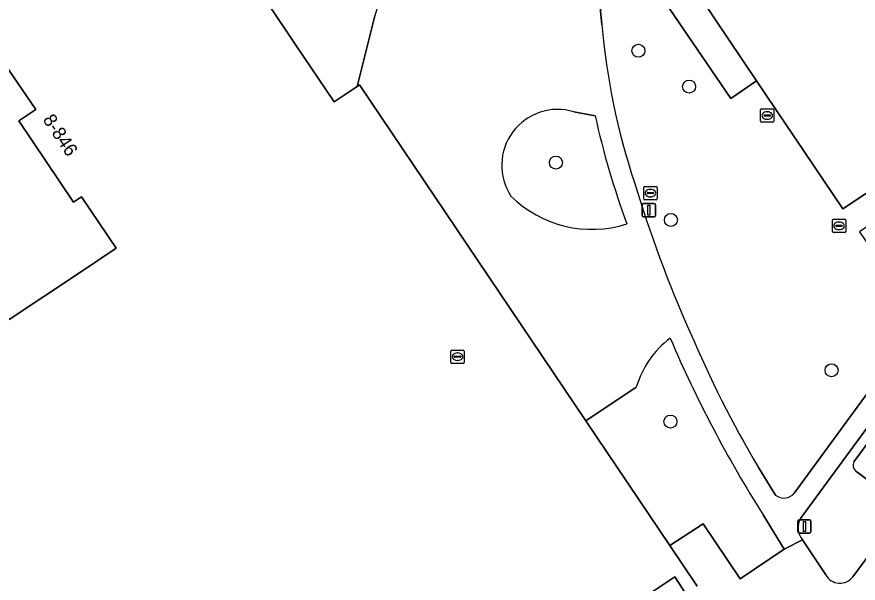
# Model space of a CAD drawing. Extents: x 159674 to 160531, y 382172 to 382904.
# Drawn here: x 159903.8 to 159966.8, y 382436.5 to 382479 of the extents above; entities that cross this region are included whole.
import ezdxf

# ---------------------------------------------------------------- set-up
doc = ezdxf.new("R2010")
doc.units = 0
for name, color, linetype in [('IMGEO_Boom', 7, 'Continuous'), ('IMGEO_Groenvoorziening', 7, 'Continuous'), ('IMGEO_Lichtmast', 7, 'Continuous'), ('IMGEO_Pand', 7, 'Continuous'), ('IMGEO_Pand_nummerreeks', 7, 'Continuous'), ('IMGEO_Parkeervlak_open', 7, 'Continuous'), ('IMGEO_Rijbaan_lokaal_open', 7, 'Continuous'), ('IMGEO_Rioolput', 7, 'Continuous'), ('IMGEO_Voetpad_gesloten', 7, 'Continuous'), ('IMGEO_Voetpad_open', 7, 'Continuous')]:
    doc.layers.add(name, color=color, linetype=linetype)

msp = doc.modelspace()

# ---------------------------------------------------------------- linework, layer by layer
at = {"layer": 'IMGEO_Boom'}
for centre in [(159950.366, 382476.465), (159954.172, 382473.778), (159944.184, 382468.073), (159952.803, 382463.765), (159964.851, 382452.486), (159952.769, 382448.638)]:
    msp.add_circle(centre, 0.489, dxfattribs=at)
at = {"layer": 'IMGEO_Groenvoorziening'}
for points in [[(159981.273, 382465.667), (159991.678, 382480.008), (159991.992, 382480.211), (159996.032, 382477.439), (159996.152, 382477.512), (159986.689, 382484.462), (159983.444, 382482.349), (159980.187, 382487.175), (159978.552, 382485.987), (159984.462, 382477.186), (159972.103, 382468.865), (159965.701, 382464.59), (159959.223, 382474.207), (159957.306, 382472.872), (159952.667, 382479.665), (159953.001, 382479.864), (159952.294, 382480.975), (159952.353, 382481.014), (159951.853, 382481.903), (159947.34, 382481.538), (159947.627, 382478.436)], [(159920.894, 382482.597), (159924.587, 382477.025), (159924.687, 382476.874), (159927.556, 382472.629), (159929.284, 382473.78), (159930.626, 382479.087)], [(159947.126, 382471.589), (159945.534, 382471.883)], [(159983.301, 382457.947), (159982.838, 382458.301), (159982.702, 382459.015), (159983.343, 382459.872), (159980.738, 382461.834), (159979.204, 382464.122), (159962.528, 382441.377)], [(159966.518, 382445.61), (159976.477, 382459.119)], [(159962.082, 382443.294), (159969.303, 382453.181), (159971.096, 382455.701)], [(159950.212, 382451.214), (159946.417, 382448.7)], [(159946.417, 382448.7), (159952.717, 382439.336), (159955.221, 382440.97), (159958.003, 382436.844), (159961.289, 382439.079), (159959.711, 382441.653)], [(159959.365, 382445.206), (159960.65, 382443.114)], [(159969.816, 382442.599), (159966.663, 382444.93)], [(159966.443, 382436.997), (159968.211, 382439.403), (159970.077, 382441.998)], [(159962.665, 382439.764), (159964.416, 382437.134)]]:
    msp.add_lwpolyline(points, dxfattribs=at)
for centre, radius, start, end in [((159999.331, 382482.921), 51.898, 184.95794, 198.35432), ((159944.322, 382467.864), 4.197, 73.2191, 213.32862), ((160010.525, 382485.679), 64.946, 192.53022, 200.00048), ((160041.512, 382494.145), 95.504, 196.77657, 203.95294), ((159946.893, 382471.723), 8.658, 225.40624, 287.49547), ((160032.462, 382488.485), 84.949, 202.94226, 210.62886), ((159957.024, 382449.226), 7.096, 126.99514, 163.73447), ((160039.191, 382491.861), 94.01, 203.15522, 212.28086), ((159966.998, 382445.357), 0.543, 152.19272, 231.88168), ((159961.277, 382443.915), 1.017, 231.9574, 322.37142), ((159963.718, 382440.666), 1.386, 149.12437, 220.58515), ((159965.474, 382437.729), 1.214, 209.34496, 322.92183)]:
    msp.add_arc(centre, radius, start, end, dxfattribs=at)
at = {"layer": 'IMGEO_Lichtmast'}
for p, q in [((159950.659, 382464.101), (159950.659, 382464.901)), ((159950.659, 382464.901), (159950.659, 382464.101)), ((159950.759, 382465.001), (159951.549, 382465.001)), ((159951.549, 382465.001), (159950.759, 382465.001)), ((159951.649, 382464.901), (159951.649, 382464.101)), ((159951.649, 382464.101), (159951.649, 382464.901)), ((159951.549, 382464.001), (159950.759, 382464.001)), ((159950.759, 382464.001), (159951.549, 382464.001)), ((159962.314, 382440.379), (159962.314, 382441.179)), ((159962.314, 382441.179), (159962.314, 382440.379)), ((159962.414, 382441.279), (159963.204, 382441.279)), ((159963.204, 382441.279), (159962.414, 382441.279)), ((159963.304, 382441.179), (159963.304, 382440.379)), ((159963.304, 382440.379), (159963.304, 382441.179)), ((159963.204, 382440.279), (159962.414, 382440.279)), ((159962.414, 382440.279), (159963.204, 382440.279))]:
    msp.add_line(p, q, dxfattribs=at)
for points in [[(159951.079, 382464.876), (159951.229, 382464.876), (159951.229, 382464.126), (159951.079, 382464.126), (159951.079, 382464.876)], [(159962.734, 382441.154), (159962.884, 382441.154), (159962.884, 382440.404), (159962.734, 382440.404), (159962.734, 382441.154)]]:
    msp.add_lwpolyline(points, dxfattribs=at)
for centre, start, end in [((159950.759, 382464.901), 90, 180), ((159950.759, 382464.901), 90, 180), ((159951.549, 382464.901), 0, 90), ((159951.549, 382464.901), 360, 90), ((159950.759, 382464.101), 180, 270), ((159950.759, 382464.101), 180, 270), ((159951.549, 382464.101), 270, 0), ((159951.549, 382464.101), 270, 0), ((159962.414, 382441.179), 90, 180), ((159962.414, 382441.179), 90, 180), ((159963.204, 382441.179), 0, 90), ((159963.204, 382441.179), 360, 90), ((159962.414, 382440.379), 180, 270), ((159962.414, 382440.379), 180, 270), ((159963.204, 382440.379), 270, 0), ((159963.204, 382440.379), 270, 0)]:
    msp.add_arc(centre, 0.1, start, end, dxfattribs=at)
at = {"layer": 'IMGEO_Pand'}
for points in [[(159929.284, 382473.78), (159927.556, 382472.629), (159924.687, 382476.874), (159924.587, 382477.025), (159920.894, 382482.597), (159918.836, 382485.861), (159916.043, 382490.496), (159913.789, 382494.394), (159911.188, 382499.142), (159910.743, 382500), (159908.792, 382503.757), (159906.654, 382508.016), (159905.429, 382510.573), (159921.255, 382524.225), (159921.544, 382524.474), (159921.508, 382524.623), (159920.424, 382529.122), (159913.541, 382527.426), (159914.819, 382522.233), (159904.282, 382513.075), (159904.024, 382512.862), (159902.176, 382511.239)], [(159902.877, 382475.458), (159905.207, 382472.058), (159903.939, 382471.211), (159908.014, 382465.094), (159908.638, 382465.51), (159911.217, 382461.64), (159908.541, 382459.857), (159903.211, 382456.306)], [(159954.77, 382436.285), (159952.717, 382439.336), (159946.417, 382448.7), (159929.473, 382473.906), (159929.284, 382473.78)], [(159943.275, 382430.436), (159953.094, 382436.989), (159953.927, 382435.721)]]:
    msp.add_lwpolyline(points, dxfattribs=at)
msp.add_lwpolyline([(159978.552, 382485.987), (159977.69, 382487.272), (159971.108, 382497.075), (159952.337, 382484.474), (159953.275, 382483.094), (159953.953, 382482.094), (159959.223, 382474.207), (159965.701, 382464.59), (159972.103, 382468.865), (159984.462, 382477.186)], close=True, dxfattribs=at)
at = {"layer": 'IMGEO_Parkeervlak_open'}
for points in [[(159976.477, 382459.119), (159966.518, 382445.61)], [(159966.663, 382444.93), (159969.816, 382442.599)]]:
    msp.add_lwpolyline(points, dxfattribs=at)
msp.add_arc((159966.998, 382445.357), 0.543, 152.19272, 231.88168, dxfattribs=at)
at = {"layer": 'IMGEO_Rijbaan_lokaal_open'}
for points in [[(159895.482, 382461.16), (159898.286, 382456.967), (159899.47, 382457.681), (159900.383, 382456.268), (159902.344, 382457.591), (159903.211, 382456.306), (159908.541, 382459.857), (159911.217, 382461.64), (159908.638, 382465.51), (159908.014, 382465.094), (159903.939, 382471.211), (159905.207, 382472.058), (159902.877, 382475.458), (159902.43, 382475.155)], [(159981.771, 382455.825), (159980.82, 382456.527), (159975.319, 382448.954), (159970.077, 382441.998), (159968.211, 382439.403), (159966.443, 382436.997)], [(159964.416, 382437.134), (159962.665, 382439.764), (159961.289, 382439.079), (159958.003, 382436.844), (159955.221, 382440.97), (159952.717, 382439.336), (159954.77, 382436.285)], [(159953.927, 382435.721), (159953.094, 382436.989), (159943.275, 382430.436)]]:
    msp.add_lwpolyline(points, dxfattribs=at)
msp.add_arc((159965.474, 382437.729), 1.214, 209.34496, 322.92183, dxfattribs=at)
at = {"layer": 'IMGEO_Rioolput'}
for p, q in [((159959.523, 382471.174), (159959.523, 382472.026)), ((159959.598, 382472.1), (159960.45, 382472.1)), ((159960.011, 382471.88), (159960.036, 382471.88)), ((159960.524, 382472.026), (159960.524, 382471.174)), ((159960.45, 382471.1), (159959.598, 382471.1)), ((159959.782, 382471.594), (159959.782, 382471.606)), ((159960.22, 382471.557), (159959.822, 382471.557)), ((159959.825, 382471.643), (159960.223, 382471.643)), ((159960.034, 382471.32), (159960.009, 382471.32)), ((159960.266, 382471.606), (159960.266, 382471.594)), ((159950.766, 382465.358), (159950.766, 382466.21)), ((159950.841, 382466.284), (159951.693, 382466.284)), ((159951.254, 382466.064), (159951.279, 382466.064)), ((159951.767, 382466.21), (159951.767, 382465.358)), ((159951.025, 382465.778), (159951.025, 382465.79)), ((159951.463, 382465.741), (159951.065, 382465.741)), ((159951.068, 382465.827), (159951.466, 382465.827)), ((159951.277, 382465.504), (159951.252, 382465.504)), ((159951.509, 382465.79), (159951.509, 382465.778)), ((159951.693, 382465.284), (159950.841, 382465.284)), ((159964.911, 382462.9), (159964.911, 382463.752)), ((159964.986, 382463.826), (159965.838, 382463.826)), ((159965.399, 382463.606), (159965.424, 382463.606)), ((159965.912, 382463.752), (159965.912, 382462.9)), ((159965.17, 382463.32), (159965.17, 382463.332)), ((159965.608, 382463.283), (159965.21, 382463.283)), ((159965.213, 382463.369), (159965.611, 382463.369)), ((159965.422, 382463.046), (159965.397, 382463.046)), ((159965.654, 382463.332), (159965.654, 382463.32)), ((159965.838, 382462.826), (159964.986, 382462.826)), ((159936.311, 382453.08), (159936.311, 382453.932)), ((159936.386, 382454.006), (159937.238, 382454.006)), ((159936.57, 382453.5), (159936.57, 382453.512)), ((159937.008, 382453.463), (159936.61, 382453.463)), ((159936.613, 382453.549), (159937.011, 382453.549)), ((159936.799, 382453.786), (159936.824, 382453.786)), ((159937.054, 382453.512), (159937.054, 382453.5)), ((159937.312, 382453.932), (159937.312, 382453.08)), ((159937.238, 382453.006), (159936.386, 382453.006)), ((159936.822, 382453.226), (159936.797, 382453.226))]:
    msp.add_line(p, q, dxfattribs=at)
for points in [[(159959.523, 382471.174), (159959.523, 382472.026)], [(159959.598, 382472.1), (159960.45, 382472.1)], [(159960.524, 382472.026), (159960.524, 382471.174)], [(159960.45, 382471.1), (159959.598, 382471.1)], [(159950.766, 382465.358), (159950.766, 382466.21)], [(159950.841, 382466.284), (159951.693, 382466.284)], [(159951.767, 382466.21), (159951.767, 382465.358)], [(159951.693, 382465.284), (159950.841, 382465.284)], [(159964.911, 382462.9), (159964.911, 382463.752)], [(159964.986, 382463.826), (159965.838, 382463.826)], [(159965.912, 382463.752), (159965.912, 382462.9)], [(159965.838, 382462.826), (159964.986, 382462.826)], [(159936.311, 382453.08), (159936.311, 382453.932)], [(159936.386, 382454.006), (159937.238, 382454.006)], [(159937.312, 382453.932), (159937.312, 382453.08)], [(159937.238, 382453.006), (159936.386, 382453.006)]]:
    msp.add_lwpolyline(points, dxfattribs=at)
for centre, radius, start, end in [((159959.6, 382472.024), 0.0765, 91.55205, 178.44795), ((159959.6, 382472.024), 0.0765, 91.55205, 178.44795), ((159960.448, 382472.024), 0.0765, 1.55205, 88.44795), ((159960.448, 382472.024), 0.0765, 1.55205, 88.44795), ((159959.6, 382471.176), 0.0765, 181.55205, 268.44795), ((159959.6, 382471.176), 0.0765, 181.55205, 268.44795), ((159959.822, 382471.603), 0.0403, 85.87752, 175.75265), ((159959.819, 382471.593), 0.0366, 178.93798, 274.71019), ((159960.223, 382471.6), 0.043, 264.86636, 352.45326), ((159960.227, 382471.605), 0.0386, 1.73085, 96.63898), ((159960.448, 382471.176), 0.0765, 271.55205, 358.44795), ((159960.448, 382471.176), 0.0765, 271.55205, 358.44795), ((159950.843, 382466.208), 0.0765, 91.55205, 178.44795), ((159950.843, 382466.208), 0.0765, 91.55205, 178.44795), ((159951.691, 382466.208), 0.0765, 1.55205, 88.44795), ((159951.691, 382466.208), 0.0765, 1.55205, 88.44795), ((159951.065, 382465.787), 0.0403, 85.87752, 175.75265), ((159951.062, 382465.777), 0.0366, 178.93798, 274.71019), ((159951.466, 382465.784), 0.043, 264.86636, 352.45326), ((159951.47, 382465.789), 0.0386, 1.73085, 96.63898), ((159950.843, 382465.36), 0.0765, 181.55205, 268.44795), ((159950.843, 382465.36), 0.0765, 181.55205, 268.44795), ((159951.691, 382465.36), 0.0765, 271.55205, 358.44795), ((159951.691, 382465.36), 0.0765, 271.55205, 358.44795), ((159964.988, 382463.75), 0.0765, 91.55205, 178.44795), ((159964.988, 382463.75), 0.0765, 91.55205, 178.44795), ((159965.836, 382463.75), 0.0765, 1.55205, 88.44795), ((159965.836, 382463.75), 0.0765, 1.55205, 88.44795), ((159964.988, 382462.902), 0.0765, 181.55205, 268.44795), ((159964.988, 382462.902), 0.0765, 181.55205, 268.44795), ((159965.21, 382463.329), 0.0403, 85.87752, 175.75265), ((159965.207, 382463.319), 0.0366, 178.93798, 274.71019), ((159965.611, 382463.326), 0.043, 264.86636, 352.45326), ((159965.615, 382463.331), 0.0386, 1.73085, 96.63898), ((159965.836, 382462.902), 0.0765, 271.55205, 358.44795), ((159965.836, 382462.902), 0.0765, 271.55205, 358.44795), ((159936.388, 382453.93), 0.0765, 91.55205, 178.44795), ((159936.388, 382453.93), 0.0765, 91.55205, 178.44795), ((159936.61, 382453.509), 0.0403, 85.87752, 175.75265), ((159936.607, 382453.499), 0.0366, 178.93798, 274.71019), ((159937.011, 382453.506), 0.043, 264.86636, 352.45326), ((159937.015, 382453.511), 0.0386, 1.73085, 96.63898), ((159937.236, 382453.93), 0.0765, 1.55205, 88.44795), ((159937.236, 382453.93), 0.0765, 1.55205, 88.44795), ((159936.388, 382453.082), 0.0765, 181.55205, 268.44795), ((159936.388, 382453.082), 0.0765, 181.55205, 268.44795), ((159937.236, 382453.082), 0.0765, 271.55205, 358.44795), ((159937.236, 382453.082), 0.0765, 271.55205, 358.44795)]:
    msp.add_arc(centre, radius, start, end, dxfattribs=at)
for centre, major_axis, ratio, start_param, end_param in [((159960.01, 382471.6), (-0.387, 0.002), 0.722429, 4.712389, 7.853982), ((159960.035, 382471.6), (-0.39, 0.002), 0.717154, 1.570796, 4.712389), ((159951.253, 382465.784), (-0.387, 0.002), 0.722429, 4.712389, 7.853982), ((159951.278, 382465.784), (-0.39, 0.002), 0.717154, 1.570796, 4.712389), ((159965.398, 382463.326), (-0.387, 0.002), 0.722429, 4.712389, 7.853982), ((159965.423, 382463.326), (-0.39, 0.002), 0.717154, 1.570796, 4.712389), ((159936.798, 382453.506), (-0.387, 0.002), 0.722429, 4.712389, 7.853982), ((159936.823, 382453.506), (-0.39, 0.002), 0.717154, 1.570796, 4.712389)]:
    msp.add_ellipse(centre, major_axis=major_axis, ratio=ratio, start_param=start_param, end_param=end_param, dxfattribs=at)
at = {"layer": 'IMGEO_Voetpad_gesloten'}
for points in [[(159952.353, 382481.014), (159953.953, 382482.094), (159953.275, 382483.094), (159947.291, 382482.795), (159947.091, 382485.74), (159948.327, 382520.678), (159946.812, 382520.597), (159945.579, 382487.312), (159945.602, 382485.361), (159945.842, 382481.317), (159933.391, 382483.848), (159942.071, 382519.651), (159940.505, 382519.281), (159936.306, 382502.078), (159935.066, 382496.883), (159931.026, 382480.571), (159930.626, 382479.087), (159929.284, 382473.78), (159929.473, 382473.906), (159946.417, 382448.7), (159950.212, 382451.214)], [(159947.627, 382478.436), (159947.34, 382481.538), (159951.853, 382481.903), (159952.353, 382481.014)], [(159945.534, 382471.883), (159947.126, 382471.589)], [(159962.528, 382441.377), (159979.204, 382464.122), (159980.738, 382461.834), (159983.343, 382459.872), (159984.461, 382461.389), (159982.172, 382463.099), (159977.404, 382470.015), (159975.834, 382468.946), (159973.024, 382467.034), (159966.95, 382462.888), (159971.088, 382456.766)], [(159971.096, 382455.701), (159969.303, 382453.181), (159962.082, 382443.294)], [(159960.65, 382443.114), (159959.365, 382445.206)], [(159959.711, 382441.653), (159961.289, 382439.079), (159962.665, 382439.764)]]:
    msp.add_lwpolyline(points, dxfattribs=at)
for centre, radius, start, end in [((159999.331, 382482.921), 51.898, 184.95794, 198.35432), ((159944.322, 382467.864), 4.197, 73.2191, 213.32862), ((160010.525, 382485.679), 64.946, 192.53022, 200.00048), ((160041.512, 382494.145), 95.504, 196.77657, 203.95294), ((159946.893, 382471.723), 8.658, 225.40624, 287.49547), ((160032.462, 382488.485), 84.949, 202.94226, 210.62886), ((159957.024, 382449.226), 7.096, 126.99514, 163.73447), ((160039.191, 382491.861), 94.01, 203.15522, 212.28086), ((159961.277, 382443.915), 1.017, 231.9574, 322.37142), ((159963.718, 382440.666), 1.386, 149.12437, 220.58515)]:
    msp.add_arc(centre, radius, start, end, dxfattribs=at)
at = {"layer": 'IMGEO_Voetpad_open'}
msp.add_lwpolyline([(159953.953, 382482.094), (159952.353, 382481.014), (159952.294, 382480.975), (159953.001, 382479.864), (159952.667, 382479.665), (159957.306, 382472.872), (159959.223, 382474.207)], close=True, dxfattribs=at)

# ---------------------------------------------------------------- texts
at = {"layer": 'IMGEO_Pand_nummerreeks'}
msp.add_text('8-846', height=1, rotation=303.67366, dxfattribs=at).set_placement((159905.687, 382471.292))

doc.saveas('drawing.dxf')
